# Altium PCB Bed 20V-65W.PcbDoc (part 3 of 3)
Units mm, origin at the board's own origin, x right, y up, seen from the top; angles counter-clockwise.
Board outline 82.02 x 73.67 mm, 2 copper layers (Top Layer, Bottom Layer); 0 components, 1 nets, 2 pads, 0 vias.
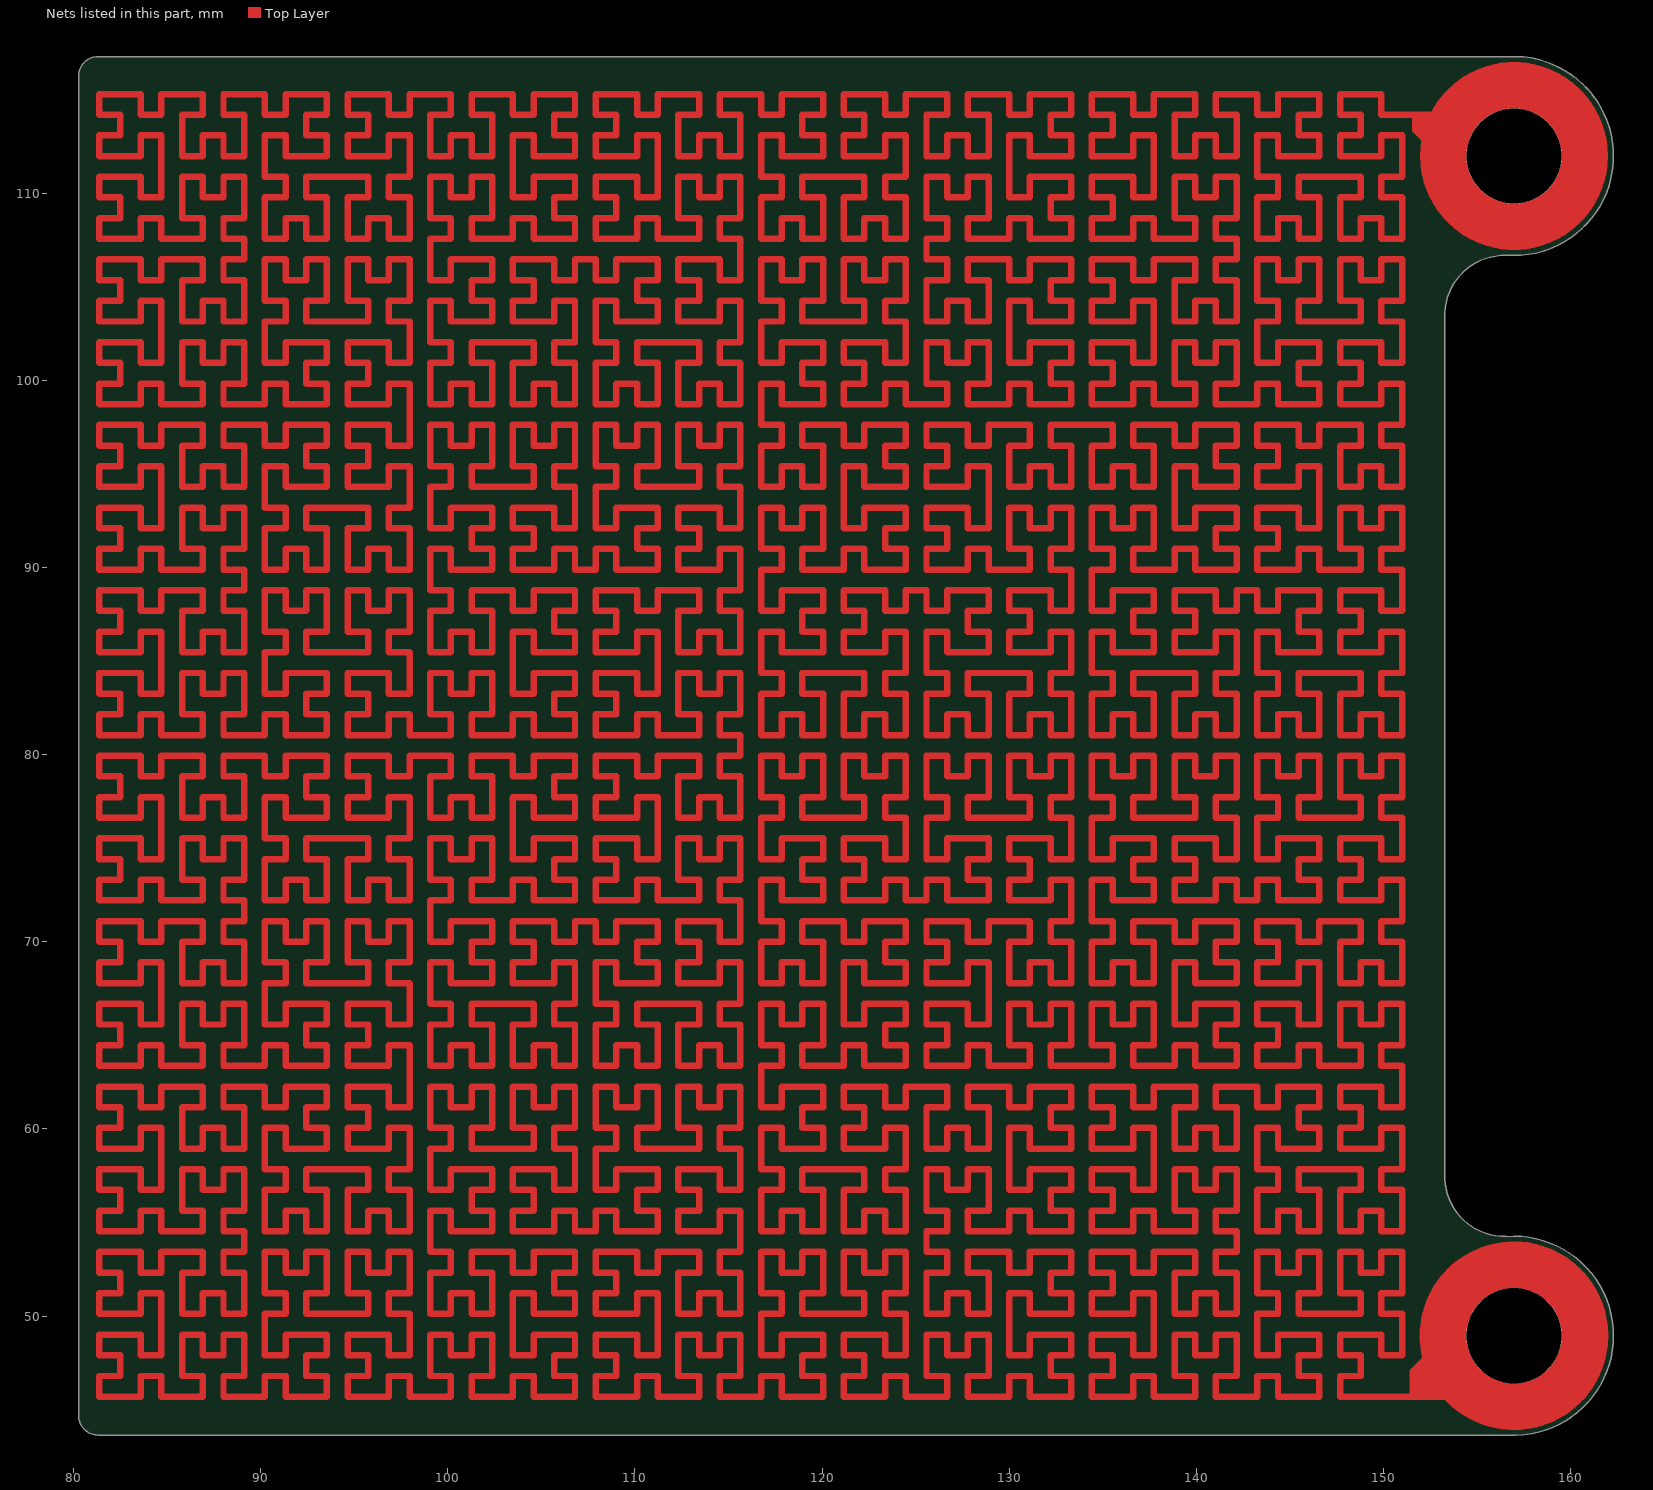
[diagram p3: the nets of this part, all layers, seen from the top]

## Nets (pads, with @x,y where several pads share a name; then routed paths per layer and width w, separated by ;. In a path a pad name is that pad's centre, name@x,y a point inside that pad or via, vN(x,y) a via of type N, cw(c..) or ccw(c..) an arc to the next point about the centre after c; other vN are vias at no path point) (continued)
Bed20V: (continued)
  Top Layer w0.346: 136.628,110.878 136.628,109.774 137.733,109.774 137.733,113.088 136.628,113.088 136.628,111.983 134.418,111.983 134.418,113.088 135.523,113.088 135.523,114.193 134.418,114.193 134.418,115.298 136.628,115.298 136.628,114.193 137.733,114.193 137.733,115.298 139.943,115.298 139.943,114.193 138.838,114.193 138.838,111.983 139.943,111.983 139.943,113.088 141.048,113.088 141.048,111.983 142.152,111.983 142.152,114.193 141.048,114.193 141.048,115.298 143.257,115.298 143.257,114.193 144.362,114.193 144.362,115.298 146.572,115.298 146.572,114.193 145.467,114.193 145.467,113.088 146.572,113.088 146.572,111.983 144.362,111.983 144.362,113.088 143.257,113.088 143.257,110.878 144.362,110.878 144.362,109.774 143.257,109.774 143.257,107.564 144.362,107.564 144.362,108.669 145.467,108.669 145.467,107.564 146.572,107.564 146.572,109.774 145.467,109.774 145.467,110.878 148.782,110.878 148.782,109.774 147.677,109.774 147.677,107.564 148.782,107.564 148.782,108.669 149.887,108.669 149.887,107.564 150.992,107.564 150.992,109.774 149.887,109.774 149.887,110.878 150.992,110.878 150.992,113.088 149.887,113.088 149.887,111.983 147.677,111.983 147.677,113.088 148.782,113.088 148.782,114.193 147.677,114.193 147.677,115.298 149.887,115.298 149.887,114.193 151.689,114.193 ; 151.689,114.193 151.968,114.193 ; 151.689,114.193 151.689,113.386 151.968,113.106 ; 151.841,45.689 152.121,45.689 ; 151.968,113.106 151.968,114.193 ; 151.968,114.193 152.222,114.193 ; 152.121,45.689 152.4,45.689 ; 152.222,114.193 152.451,114.193 ; 152.4,45.689 152.679,45.689 ; 152.451,114.193 152.756,114.193 ; 152.679,45.689 152.959,45.689 ; 152.756,114.193 152.984,114.193 ; 152.959,45.689 152.959,46.018 ; 152.959,46.018 152.959,46.33
  Top Layer w2.5: 160.741,111.989 ccw(c156.972,111.989) 160.741,111.989 ; 160.764,48.947 ccw(c156.972,48.947) 160.764,48.947

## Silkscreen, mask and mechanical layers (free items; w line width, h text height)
Bottom Overlay:
  drawing of 7 lines, arcs and shapes, not listed
Top Solder:
  circle w2.5: c156.972,111.989 r3.769
  circle w2.5: c156.972,48.947 r3.769
Mechanical 1:
  lines w0.5: 81.28,43.637 157.099,43.637 ; 81.305,43.638 cw(c81.318,44.691) 80.265,44.704 80.331,116.057 cw(c81.489,116.071) 81.475,117.23 157.099,117.298 ; 153.272,57.329 ccw(c156.486,57.471) 156.54,54.255 ; 153.272,57.355 153.272,103.606 cw(c156.485,103.464) 156.54,106.68 ; 156.564,54.248 cw(c156.972,48.947) 162.289,48.947 cw(c156.972,48.947) 157.099,43.631 ; 156.564,106.687 ccw(c156.972,111.989) 162.289,111.989 ccw(c156.972,111.989) 157.099,117.304
Mechanical 15:
  lines w0.003: 115.976,80.628 115.977,80.629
